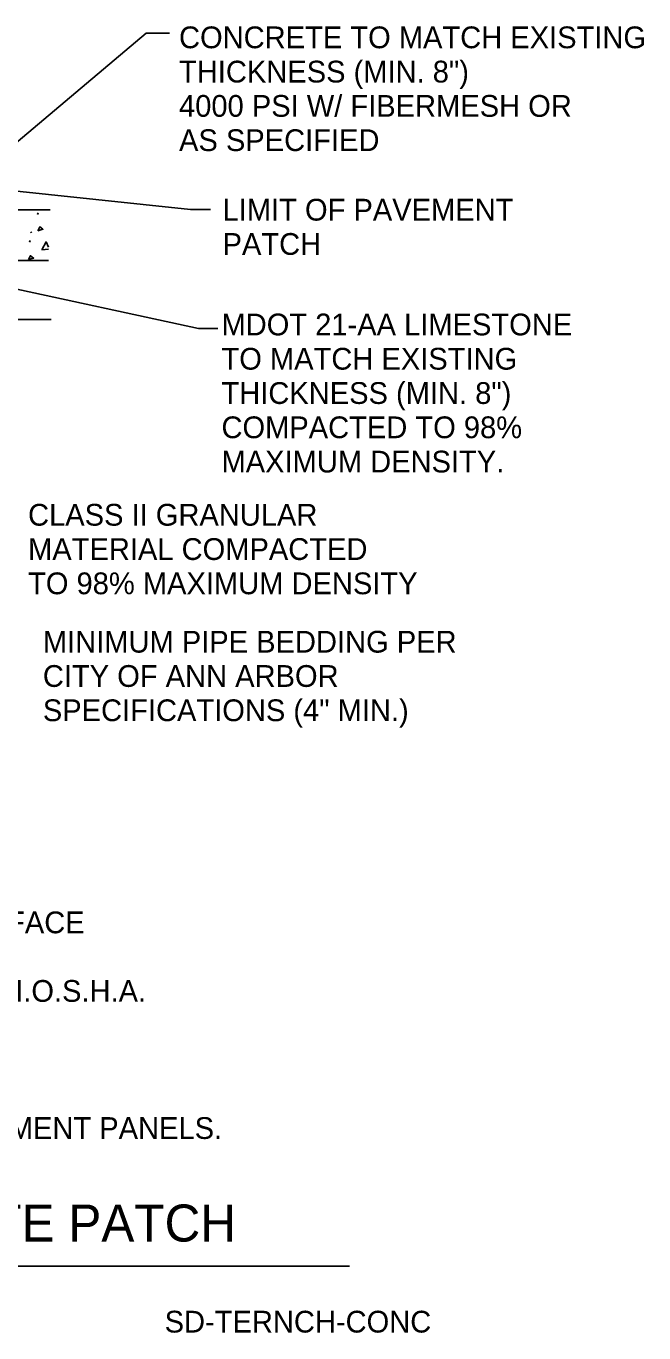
# Model space of a CAD drawing. Extents: x 9992 to 10079.1, y 10009.9 to 10072.5.
# Drawn here: x 10049.4 to 10079.1, y 10009.9 to 10072.5 of the extents above; entities that cross this region are included whole.
import ezdxf

# ---------------------------------------------------------------- set-up
doc = ezdxf.new("R2010")
doc.units = 0
for name, color, linetype in [('G-ANNO-TEXT', 7, 'Continuous'), ('G-ANNO-TTXT', 7, 'Continuous'), ('G-DETL-PATT', 7, 'Continuous')]:
    doc.layers.add(name, color=color, linetype=linetype)

msp = doc.modelspace()

# ---------------------------------------------------------------- linework, layer by layer
at = {"layer": 'G-ANNO-TEXT'}
for p, q in [((10048.203, 10063.733), (10050.573, 10063.733)), ((10048.226, 10061.294), (10050.481, 10061.294)), ((10048.226, 10058.479), (10050.62, 10058.479)), ((10007.603, 10013.063), (10064.936, 10013.063))]:
    msp.add_line(p, q, dxfattribs=at)
for points in [[(10045.34, 10063.93), (10055.169, 10072.198), (10056.297, 10072.198)], [(10048.21, 10064.706), (10057.299, 10063.754), (10058.262, 10063.754)], [(10048.226, 10060.082), (10057.684, 10058.044), (10058.62, 10058.044)]]:
    msp.add_lwpolyline(points, dxfattribs=at)
at = {"layer": 'G-DETL-PATT'}
for p, q in [((10049.964, 10063.513), (10049.994, 10063.58)), ((10049.636, 10062.678), (10049.666, 10062.633)), ((10049.58, 10062.186), (10049.61, 10062.253))]:
    msp.add_line(p, q, dxfattribs=at)
for points in [[(10049.979, 10062.73), (10050.068, 10062.916), (10050.217, 10062.804), (10049.979, 10062.73)], [(10050.165, 10061.813), (10050.366, 10062.194), (10050.481, 10061.938)], [(10050.481, 10061.84), (10050.172, 10061.813)], [(10049.528, 10061.344), (10049.617, 10061.53), (10049.766, 10061.418), (10049.528, 10061.344)]]:
    msp.add_lwpolyline(points, dxfattribs=at)

# ---------------------------------------------------------------- texts
at = {"layer": 'G-ANNO-TEXT'}
for s, p in [('CONCRETE TO MATCH EXISTING ', (10056.751, 10071.482)), ('THICKNESS (MIN. 8")', (10056.751, 10069.838)), ('4000 PSI W/ FIBERMESH OR ', (10056.751, 10068.194)), ('AS SPECIFIED', (10056.751, 10066.55)), ('LIMIT OF PAVEMENT', (10058.84, 10063.216)), ('PATCH', (10058.84, 10061.572)), ('MDOT 21-AA LIMESTONE ', (10058.788, 10057.711)), ('TO MATCH EXISTING ', (10058.788, 10056.067)), ('THICKNESS (MIN. 8") ', (10058.788, 10054.423)), ('COMPACTED TO 98% ', (10058.788, 10052.779)), ('MAXIMUM DENSITY.', (10058.788, 10051.135)), ('CLASS II GRANULAR', (10049.505, 10048.584)), ('MATERIAL COMPACTED', (10049.505, 10046.94)), ('TO 98% MAXIMUM DENSITY', (10049.505, 10045.296)), ('MINIMUM PIPE BEDDING PER', (10050.215, 10042.496)), ('CITY OF ANN ARBOR', (10050.215, 10040.852)), ('SPECIFICATIONS (4" MIN.)', (10050.215, 10039.208)), ('1) TRENCH DETAILS SHOW TYPE OF BACKFILL AND SURFACE ', (10010.1, 10029.036)), ('2) ALL TRENCHING TO CONFORM TO ALL APPLICABLE M.I.O.S.H.A. ', (10010.1, 10025.748)), ('4) REMOVE & REPLACE HALF OR FULL CONCRETE PAVEMENT PANELS.', (10010.1, 10019.172)), ('SD-TERNCH-CONC', (10056.06, 10009.886))]:
    msp.add_text(s, height=1.044, dxfattribs=at).set_placement(p)
at = {"layer": 'G-ANNO-TTXT'}
msp.add_text('UTILITY TRENCH WITH  CONCRETE PATCH', height=1.776, dxfattribs=at).set_placement((10010.009, 10014.25))

doc.saveas('drawing.dxf')
